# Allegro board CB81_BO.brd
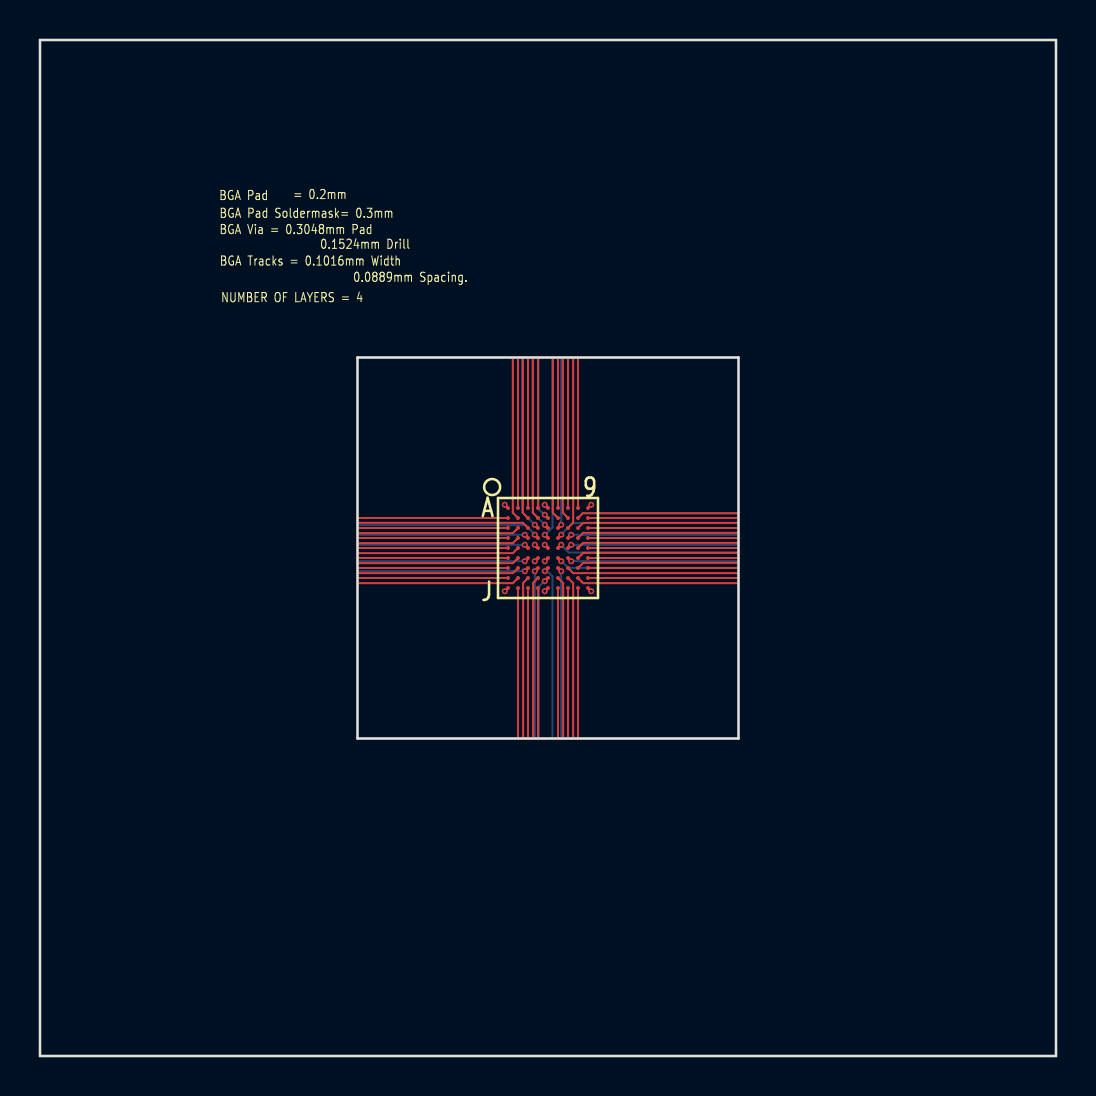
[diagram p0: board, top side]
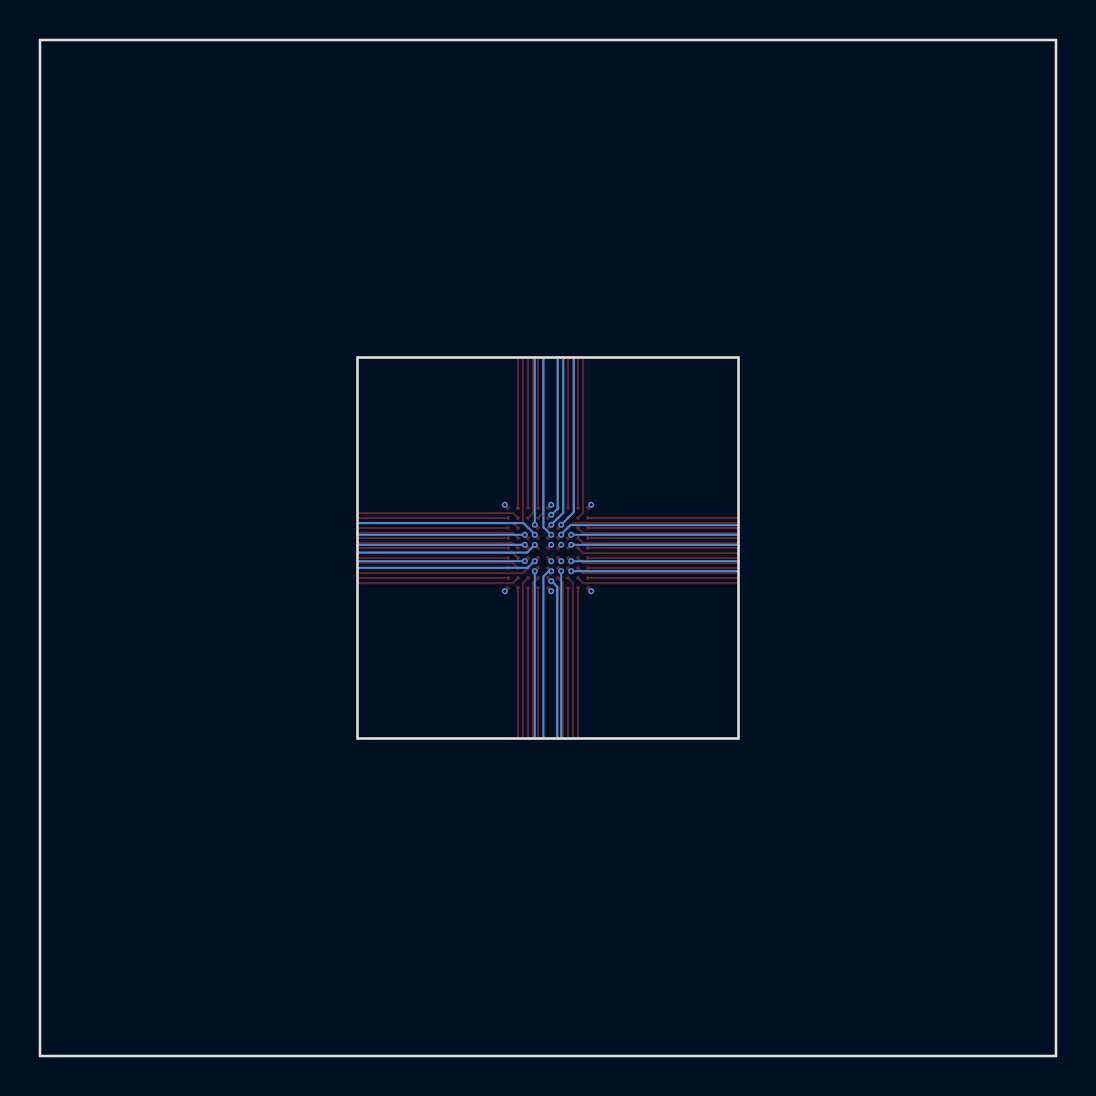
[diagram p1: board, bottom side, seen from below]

Outline 50.8 x 50.8 mm; copper layers: TOP, GND, POWER, BOTTOM. Coordinates in mm from the lower left corner of the outline.
Outline path: 0,50.8 0,0 50.8,0 50.8,50.8 0,50.8 ; 15.87,34.92 15.87,15.87 34.92,15.87 34.92,34.92 15.87,34.92

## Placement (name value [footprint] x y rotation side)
U1  -  [BGA5X5-81_0-2MM]  25.4 25.4 0 top

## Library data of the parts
U1 = BGA5X5-81_0-2MM

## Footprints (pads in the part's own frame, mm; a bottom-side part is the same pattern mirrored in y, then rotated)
BGA5X5-81_0-2MM
  round 0.2 smd: A1(-2,2) A2(-1.5,2) A3(-1,2) A4(-0.5,2) A5(0,2) A6(0.5,2) A7(1,2) A8(1.5,2) A9(2,2) B1(-2,1.5) B2(-1.5,1.5) B3(-1,1.5) B4(-0.5,1.5) B5(0,1.5) B6(0.5,1.5) B7(1,1.5) B8(1.5,1.5) B9(2,1.5) C1(-2,1) C2(-1.5,1) C3(-1,1) C4(-0.5,1) C5(0,1) C6(0.5,1) C7(1,1) C8(1.5,1) C9(2,1) D1(-2,0.5) D2(-1.5,0.5) D3(-1,0.5) D4(-0.5,0.5) D5(0,0.5) D6(0.5,0.5) D7(1,0.5) D8(1.5,0.5) D9(2,0.5) E1(-2,0) E2(-1.5,0) E3(-1,0) E4(-0.5,0) E5(0,0) E6(0.5,0) E7(1,0) E8(1.5,0) E9(2,0) F1(-2,-0.5) F2(-1.5,-0.5) F3(-1,-0.5) F4(-0.5,-0.5) F5(0,-0.5) F6(0.5,-0.5) F7(1,-0.5) F8(1.5,-0.5) F9(2,-0.5) G1(-2,-1) G2(-1.5,-1) G3(-1,-1) G4(-0.5,-1) G5(0,-1) G6(0.5,-1) G7(1,-1) G8(1.5,-1) G9(2,-1) H1(-2,-1.5) H2(-1.5,-1.5) H3(-1,-1.5) H4(-0.5,-1.5) H5(0,-1.5) H6(0.5,-1.5) H7(1,-1.5) H8(1.5,-1.5) H9(2,-1.5) J1(-2,-2) J2(-1.5,-2) J3(-1,-2) J4(-0.5,-2) J5(0,-2) J6(0.5,-2) J7(1,-2) J8(1.5,-2) J9(2,-2)

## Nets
GND: U1.A1 U1.A9 U1.E4 U1.E5 U1.F4 U1.F5 U1.J1 U1.J9
VCC: U1.A5 U1.J5
A2: U1.A2
A3: U1.A3
A4: U1.A4
A6: U1.A6
A7: U1.A7
A8: U1.A8
B1: U1.B1
B2: U1.B2
B3: U1.B3
B4: U1.B4
B5: U1.B5
B6: U1.B6
B7: U1.B7
B8: U1.B8
C1: U1.C1
C2: U1.C2
C3: U1.C3
C4: U1.C4
C5: U1.C5
C6: U1.C6
C7: U1.C7
C8: U1.C8
C9: U1.C9
D1: U1.D1
D2: U1.D2
D3: U1.D3
D4: U1.D4
D5: U1.D5
D6: U1.D6
D7: U1.D7
D8: U1.D8
D9: U1.D9
E1: U1.E1
E2: U1.E2
E3: U1.E3
E6: U1.E6
E7: U1.E7
E8: U1.E8
E9: U1.E9
F1: U1.F1
F2: U1.F2
F3: U1.F3
F6: U1.F6
F7: U1.F7
F8: U1.F8
F9: U1.F9
G1: U1.G1
G2: U1.G2
G3: U1.G3
G4: U1.G4
G5: U1.G5
G6: U1.G6
G7: U1.G7
G8: U1.G8
G9: U1.G9
H1: U1.H1
H2: U1.H2
H3: U1.H3
H4: U1.H4
H5: U1.H5
H6: U1.H6
H7: U1.H7
H8: U1.H8
H9: U1.H9
J2: U1.J2
J3: U1.J3
J4: U1.J4
J6: U1.J6
J7: U1.J7
J8: U1.J8
VPP 2V5: U1.B9

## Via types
v1: diameter 0.305, hole 0.152, TOP to BOTTOM, 30 vias

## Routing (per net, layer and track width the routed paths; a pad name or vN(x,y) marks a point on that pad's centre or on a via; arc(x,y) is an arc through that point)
GND: length 1.8
  TOP w0.102: v1(25.24,24.74) U1.F5 ; v1(23.24,23.24) U1.J1 ; v1(27.56,23.24) U1.J9 ; v1(24.74,24.74) U1.F4 ; v1(24.74,25.56) U1.E4 ; v1(25.24,25.56) U1.E5 ; v1(27.56,27.56) U1.A9 ; v1(23.24,27.56) U1.A1
VCC: length 0.4
  TOP w0.102: v1(25.24,27.56) U1.A5 ; v1(25.24,23.24) U1.J5
A2: length 7.5
  TOP w0.102: U1.A2 23.9,34.9
A3: length 7.5
  TOP w0.102: U1.A3 24.4,34.9
A4: length 7.5
  TOP w0.102: U1.A4 24.9,34.9
A6: length 7.5
  TOP w0.102: U1.A6 25.9,34.9
A7: length 7.5
  TOP w0.102: U1.A7 26.4,34.9
A8: length 7.5
  TOP w0.102: U1.A8 26.9,34.9
B1: length 7.5
  TOP w0.102: U1.B1 15.9,26.9
B2: length 8.1
  TOP w0.102: 23.64,34.92 23.64,27.16 U1.B2
B3: length 8.1
  TOP w0.102: U1.B3 24.14,27.16 24.14,34.92
B4: length 8.1
  TOP w0.102: 24.64,34.92 24.64,27.16 U1.B4
B5: length 8.3
  TOP w0.102: v1(25.24,27.06) U1.B5
  BOTTOM w0.102: v1(25.24,27.06) 25.21,27.06 24.92,27.36 24.92,34.95
B6: length 8.1
  TOP w0.102: U1.B6 25.64,27.16 25.64,34.92
B7: length 8.1
  TOP w0.102: U1.B7 26.14,27.16 26.14,34.92
B8: length 8.1
  TOP w0.102: 34.92,27.14 27.14,27.14 U1.B8
C1: length 7.5
  TOP w0.102: U1.C1 15.9,26.4
C2: length 8.1
  TOP w0.102: 15.87,26.14 23.64,26.14 U1.C2
C3: length 8.6
  TOP w0.102: U1.C3 24.14,26.66 15.87,26.66
C4: length 8.9
  TOP w0.102: v1(24.74,26.56) U1.C4
  BOTTOM w0.102: v1(24.74,26.56) 24.1,27.2 24.1,34.94
C5: length 8.9
  TOP w0.102: v1(25.24,26.56) U1.C5
  BOTTOM w0.102: 24.64,34.94 24.64,27.16 v1(25.24,26.56)
C6: length 8.6
  TOP w0.102: v1(26.06,26.56) U1.C6
  BOTTOM w0.102: v1(26.06,26.56) 26.06,34.94
C7: length 8.6
  TOP w0.102: 26.66,34.86 26.66,26.66 U1.C7
C8: length 8.1
  TOP w0.102: U1.C8 27.16,26.66 34.92,26.66
C9: length 7.5
  TOP w0.102: U1.C9 34.9,26.4
D1: length 7.5
  TOP w0.102: U1.D1 15.9,25.9
D2: length 8.1
  TOP w0.102: 15.87,25.64 23.64,25.64 U1.D2
D3: length 8.6
  TOP w0.102: v1(24.24,26.06) U1.D3
  BOTTOM w0.102: v1(24.24,26.06) 15.86,26.06
D4: length 9.3
  TOP w0.102: v1(24.74,26.06) U1.D4
  BOTTOM w0.102: v1(24.74,26.06) 24.74,26.08 24.28,26.54 15.87,26.54
D5: length 9.2
  TOP w0.102: v1(25.24,26.06) U1.D5
  BOTTOM w0.102: 25.63,34.9 25.63,26.44 25.25,26.06 v1(25.24,26.06)
D6: length 9.3
  TOP w0.102: v1(26.06,26.06) U1.D6
  BOTTOM w0.102: v1(26.06,26.06) 26.06,26.08 26.62,26.64 34.9,26.64
D7: length 8.6
  TOP w0.102: v1(26.56,26.06) U1.D7
  BOTTOM w0.102: v1(26.56,26.06) 34.94,26.06
D8: length 8.1
  TOP w0.102: U1.D8 27.16,26.16 34.92,26.16
D9: length 7.5
  TOP w0.102: U1.D9 34.9,25.9
E1: length 7.5
  TOP w0.102: U1.E1 15.9,25.4
E2: length 8.1
  TOP w0.102: U1.E2 23.64,25.14 15.87,25.14
E3: length 8.6
  TOP w0.102: v1(24.24,25.56) U1.E3
  BOTTOM w0.102: v1(24.24,25.56) 15.86,25.56
E6: length 9.3
  TOP w0.102: v1(26.06,25.56) U1.E6
  BOTTOM w0.102: v1(26.06,25.56) 26.06,25.55 26.44,25.17 34.95,25.17
E7: length 8.6
  TOP w0.102: v1(26.56,25.56) U1.E7
  BOTTOM w0.102: v1(26.56,25.56) 34.94,25.56
E8: length 8.1
  TOP w0.102: U1.E8 27.16,25.66 34.92,25.66
E9: length 7.5
  TOP w0.102: U1.E9 34.9,25.4
F1: length 7.5
  TOP w0.102: U1.F1 15.9,24.9
F2: length 8.1
  TOP w0.102: 15.87,24.64 23.64,24.64 U1.F2
F3: length 8.6
  TOP w0.102: v1(24.24,24.74) U1.F3
  BOTTOM w0.102: v1(24.24,24.74) 15.86,24.74
F6: length 9.2
  TOP w0.102: v1(26.06,24.74) U1.F6
  BOTTOM w0.102: 34.92,24.41 26.42,24.41 26.08,24.74 v1(26.06,24.74)
F7: length 8.6
  TOP w0.102: v1(26.56,24.74) U1.F7
  BOTTOM w0.102: v1(26.56,24.74) 34.94,24.74
F8: length 8.1
  TOP w0.102: 34.92,25.16 27.16,25.16 U1.F8
F9: length 7.5
  TOP w0.102: U1.F9 34.9,24.9
G1: length 7.5
  TOP w0.102: U1.G1 15.9,24.4
G2: length 8.1
  TOP w0.102: 15.87,24.14 23.64,24.14 U1.G2
G3: length 8.6
  TOP w0.102: v1(24.24,24.24) U1.G3
  BOTTOM w0.102: v1(24.24,24.24) 15.89,24.24
G4: length 8.6
  TOP w0.102: v1(24.74,24.24) U1.G4
  BOTTOM w0.102: v1(24.74,24.24) 24.74,15.9
G5: length 8.8
  TOP w0.102: v1(25.24,24.24) U1.G5
  BOTTOM w0.102: 25.63,15.87 25.63,23.98 25.37,24.24 v1(25.24,24.24)
G6: length 8.6
  TOP w0.102: v1(26.06,24.24) U1.G6
  BOTTOM w0.102: v1(26.06,24.24) 26.06,15.86
G7: length 8.6
  TOP w0.102: U1.G7 26.66,24.14 34.9,24.14
G8: length 8.1
  TOP w0.102: U1.G8 27.16,24.66 34.92,24.66
G9: length 7.5
  TOP w0.102: U1.G9 34.9,24.4
H1: length 7.5
  TOP w0.102: U1.H1 15.9,23.9
H2: length 8.1
  TOP w0.102: U1.H2 23.64,23.64 15.88,23.64
H3: length 8.1
  TOP w0.102: 24.16,15.87 24.16,23.66 U1.H3
H4: length 8.1
  TOP w0.102: U1.H4 24.66,23.66 24.66,15.87
H5: length 8.2
  TOP w0.102: v1(25.24,23.74) U1.H5
  BOTTOM w0.102: v1(25.24,23.74) 25.21,23.74 24.94,23.47 24.94,15.9
H6: length 8.1
  TOP w0.102: U1.H6 26.16,23.64 26.16,15.87
H7: length 8.1
  TOP w0.102: U1.H7 26.66,23.64 26.66,15.87
H8: length 8.1
  TOP w0.102: 34.92,23.64 27.16,23.64 U1.H8
H9: length 7.5
  TOP w0.102: U1.H9 34.9,23.9
J2: length 7.5
  TOP w0.102: U1.J2 23.9,15.9
J3: length 7.5
  TOP w0.102: U1.J3 24.4,15.9
J4: length 7.5
  TOP w0.102: U1.J4 24.9,15.9
J6: length 7.5
  TOP w0.102: U1.J6 25.9,15.9
J7: length 7.5
  TOP w0.102: U1.J7 26.4,15.9
J8: length 7.5
  TOP w0.102: U1.J8 26.9,15.9
VPP 2V5: length 7.5
  TOP w0.102: U1.B9 34.9,26.9

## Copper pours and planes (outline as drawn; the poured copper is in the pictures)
GND on GND: 22.99,27.81 22.99,22.99 27.81,22.99 27.81,27.81
VCC on POWER: 22.99,27.81 22.99,22.99 27.81,22.99 27.81,27.81

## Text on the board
Ref Des/Silkscreen Top: BGA Pad | BGA Pad Soldermask= 0.3mm | BGA Via = 0.3048mm Pad | BGA Tracks = 0.1016mm Width | NUMBER OF LAYERS = 4 | = 0.2mm | 0.1524mm Drill | 0.0889mm Spacing.
